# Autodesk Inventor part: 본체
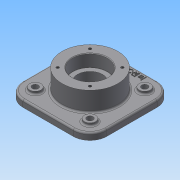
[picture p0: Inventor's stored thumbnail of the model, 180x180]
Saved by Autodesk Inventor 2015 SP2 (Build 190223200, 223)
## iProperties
Created: 2015-07
Part Number: 본체
Material: 일반
Document SubType Name: Modeling
Designer: AMC
Density: 1 g/cm^3
Appearance: 기본값
Mass: 515.417 g
Surface Area: 782.713 cm^2
Volume: 515.417 cm^3
Author: AMC
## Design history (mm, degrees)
sketch "스케치1"
  geometry: L1 (-75, -75)-(75, -75); L2 (75, -75)-(75, 75); L3 (75, 75)-(-75, 75); L4 (-75, 75)-(-75, -75); L5 (-75, -75)-(75, 75); L6 (75, -75)-(-75, 75); 1 further point
  constraints: 12 end point, 2 midpoint, 2 parallel, 1 horizontal, 1 perpendicular
  dimensions: "d0" = 150 distance of L3.end L2.end; "d1" = 150 distance of L2.end L1.end
extrude "돌출1" new body sketch "스케치1" distance "d2" = 12; taper "d3" = 0 deg
sketch "스케치2"
  geometry: C1 r 50 at (0, 0); 1 further point
  constraints: 1 centre point, 1 coincident
  dimensions: "d4" = 100 diameter of C1
extrude "돌출2" join sketch "스케치2" distance "d5" = 47; taper "d7" = 0 deg; dims "d6" = 23, "d8" = 0
sketch "스케치3"
  geometry: L1 (75, 75)-(-75, 75) reference; L2 (-75, 75)-(-75, -75) reference; L3 (75, -75)-(75, 75) reference; L4 (-75, -75)-(75, -75) reference; L5 (-49, -49)-(-49, 49); L6 (-49, 49)-(49, 49); L7 (49, 49)-(49, -49); L8 (49, -49)-(-49, -49); C1 r 10 at (-49, 49); C2 r 10 at (49, 49); C3 r 10 at (49, -49); C4 r 10 at (-49, -49); 1 further point
  constraints: 8 end point, 4 centre point, 4 coincident, 3 other
  dimensions: "d9" = 26 distance between parallel lines of L2 L5; "d10" = 20 diameter of C1; "d11" = 20 diameter of C2; "d12" = 20 diameter of C3; "d13" = 20 diameter of C4
extrude "돌출3" join sketch "스케치3" distance "d14" = 5; taper "d15" = 0 deg
hole "구멍1" diameter "d18" = 11; stored, may be unused: countersink angle "d22" = 90 deg, drill point angle "d24" = 0 deg; dims "d19" = 6, "d20" = 4, "d21" = 2, "d23" = 8, "d104" = 10, "d105" = 10
hole "구멍2" diameter "d27" = 11; stored, may be unused: countersink angle "d31" = 90 deg, drill point angle "d33" = 0 deg; dims "d25" = 10, "d26" = 10, "d28" = 6, "d29" = 4, "d30" = 2, "d32" = 8
hole "구멍3" diameter "d36" = 11; stored, may be unused: countersink angle "d40" = 90 deg, drill point angle "d42" = 0 deg; dims "d34" = 10, "d35" = 10, "d37" = 6, "d38" = 4, "d39" = 2, "d41" = 8
hole "구멍4" diameter "d45" = 11; stored, may be unused: countersink angle "d49" = 90 deg, drill point angle "d51" = 0 deg; dims "d43" = 10, "d44" = 10, "d46" = 6, "d47" = 4, "d48" = 2, "d50" = 8
hole "구멍5" diameter "d54" = 45; stored, may be unused: countersink angle "d58" = 90 deg, drill point angle "d60" = 0 deg; dims "d52" = 10, "d53" = 10, "d55" = 6, "d56" = 62, "d57" = 22, "d59" = 8
hole "구멍6" diameter "d63" = 45; stored, may be unused: countersink angle "d67" = 90 deg, drill point angle "d69" = 0 deg; dims "d61" = 10, "d62" = 10, "d64" = 6, "d65" = 62, "d66" = 22, "d68" = 8
sketch "스케치4"
  geometry: L1 (0, 0)-(41, 0); L2 (0, 0)-(28.991, 28.991); A1 r 41 centre (0, 0) between (41, 0) and (28.991, 28.991); 1 further point
  constraints: 4 end point, 2 point on circle, 1 centre point, 1 coincident, 1 horizontal
  dimensions: "d70" = 82 diameter of A1; "d71" = 45 deg angle of L1 L2
hole "구멍7" sketch "스케치4" at (28.991, 28.991) diameter "d72" = 4.917; stored, may be unused: countersink angle "d76" = 90 deg, drill point angle "d78" = 118 deg; dims "d73" = 10, "d74" = 62, "d75" = 22, "d77" = 13
sketch "스케치5"
  geometry: L1 (0, 0)-(41, 0); L2 (0, 0)-(28.991, 28.991); A1 r 41 centre (0, 0) between (28.991, 28.991) and (41, 0); 1 further point
  constraints: 4 end point, 2 point on circle, 1 centre point, 1 coincident, 1 horizontal
  dimensions: "d82" = 82 diameter of A1; "d83" = 45 deg angle of L1 L2
hole "구멍8" sketch "스케치5" at (28.991, 28.991) diameter "d84" = 4.917; stored, may be unused: countersink angle "d88" = 90 deg, drill point angle "d90" = 118 deg; dims "d85" = 10, "d86" = 62, "d87" = 22, "d89" = 13
fillet "모깎기1" dims "d94" = 30
chamfer "모따기1" distance "d95" = 1; stored, may be unused: second distance "d96" = 2, angle "d97" = 45 deg
fillet "모깎기2" dims "d98" = 3
fillet "모깎기3" dims "d99" = 0.3
fillet "모깎기4" dims "d100" = 3
sketch "스케치6"
  geometry: 2 further points
  constraints: 1 vertical alignment, 1 other
  dimensions: "d101" = 65 distance of point (0, 0) point (0, 65)
feature "엠보싱1" sketch "스케치6" dims "d0" = 150, "d1" = 150, "d102" = 1, "d103" = 0
node "솔리드1"
pattern_circular "원형 패턴1" dims angle "d80" = 360 deg
pattern_circular "원형 패턴2" dims angle "d92" = 360 deg
